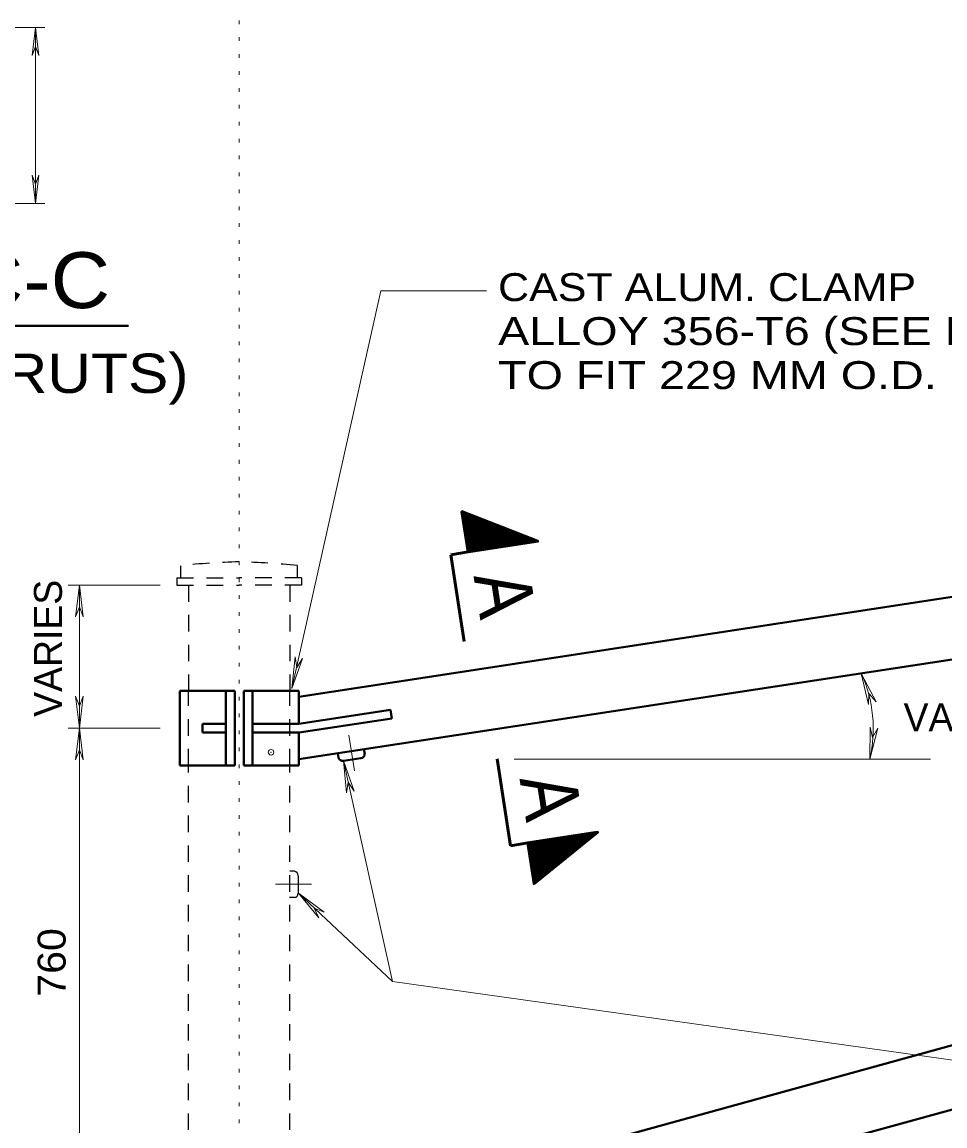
# Model space of a CAD drawing. Extents: x 312583 to 312854, y 144419 to 144597.
# Drawn here: x 312723.42 to 312748.5, y 144538.22 to 144568.25 of the extents above; entities that cross this region are included whole.
import ezdxf
from ezdxf.enums import TextEntityAlignment as Align

# ---------------------------------------------------------------- set-up
doc = ezdxf.new("R2010")
doc.units = 0
doc.header["$LTSCALE"] = 0.3
doc.header["$PDMODE"] = 32
doc.header["$PDSIZE"] = 0.15
doc.linetypes.add('DOTTED', pattern=[1.5, 0.3, -1.2])
doc.linetypes.add('SHORT_DASHED', pattern=[2.7, 1.5, -1.2])
doc.layers.add('1', color=7, linetype='Continuous', lineweight=13)

msp = doc.modelspace()

# ---------------------------------------------------------------- linework, layer by layer
at = {"layer": '1', "linetype": 'DOTTED'}
msp.add_line((312729.3174, 144527.7179), (312729.3174, 144572.2382), dxfattribs=at)
at = {"layer": '1'}
for p, q in [((312721.5945, 144568.1059), (312724.0325, 144568.1059)), ((312723.7795, 144568.1059), (312723.6875, 144567.3392)), ((312723.7795, 144563.3142), (312723.7795, 144568.1059)), ((312723.7795, 144568.1059), (312723.8715, 144567.3392)), ((312723.6875, 144567.3392), (312723.7795, 144567.5846)), ((312723.8715, 144567.3392), (312723.7795, 144567.5846)), ((312723.6875, 144564.0886), (312723.7795, 144563.8432)), ((312723.7795, 144563.3142), (312723.6875, 144564.0886)), ((312723.8715, 144564.0886), (312723.7795, 144563.8432)), ((312723.7795, 144563.3142), (312723.8715, 144564.0886)), ((312720.1991, 144563.3142), (312724.0325, 144563.3142)), ((312730.751, 144550.1199), (312733.166, 144560.9376)), ((312733.166, 144560.9376), (312736.041, 144560.9376)), ((312727.1707, 144552.9336), (312724.6685, 144552.9336)), ((312724.9722, 144552.9336), (312724.8649, 144552.0672)), ((312724.9722, 144549.0466), (312724.9722, 144552.9336)), ((312724.9722, 144552.9336), (312725.0795, 144552.0672)), ((312724.8649, 144552.0672), (312724.9722, 144552.3432)), ((312725.0795, 144552.0672), (312724.9722, 144552.3432)), ((312730.751, 144550.1199), (312730.8354, 144550.9862)), ((312730.751, 144550.1199), (312731.0424, 144550.9402)), ((312730.8354, 144550.9862), (312730.8814, 144550.6949)), ((312731.0424, 144550.9402), (312730.8814, 144550.6949)), ((312746.23, 144550.5339), (312746.4294, 144549.6829)), ((312746.23, 144550.5339), (312746.6364, 144549.7596)), ((312746.4294, 144549.6829), (312746.437, 144549.9819)), ((312746.6364, 144549.7596), (312746.437, 144549.9819)), ((312724.8649, 144549.9129), (312724.9722, 144549.6369)), ((312724.9722, 144549.0466), (312724.8649, 144549.9129)), ((312725.0795, 144549.9129), (312724.9722, 144549.6369)), ((312724.9722, 144549.0466), (312725.0795, 144549.9129)), ((312746.46, 144548.1956), (312746.4677, 144549.0696)), ((312746.4677, 144549.0696), (312746.5367, 144548.7859)), ((312727.1707, 144549.0466), (312724.6685, 144549.0466)), ((312724.9722, 144549.0466), (312724.8649, 144548.1802)), ((312724.9722, 144534.6716), (312724.9722, 144549.0466)), ((312724.9722, 144549.0466), (312725.0795, 144548.1802)), ((312732.2997, 144548.8549), (312732.453, 144547.8812)), ((312746.46, 144548.1956), (312746.6824, 144549.0389)), ((312746.6824, 144549.0389), (312746.5367, 144548.7859)), ((312724.8649, 144548.1802), (312724.9722, 144548.4562)), ((312725.0795, 144548.1802), (312724.9722, 144548.4562)), ((312733.488, 144542.1466), (312732.154, 144548.1496)), ((312732.154, 144548.1496), (312732.2384, 144547.2832)), ((312732.154, 144548.1496), (312732.4454, 144547.3292)), ((312736.7924, 144548.1956), (312748.1084, 144548.1956)), ((312732.2384, 144547.2832), (312732.2767, 144547.5746)), ((312732.4454, 144547.3292), (312732.2767, 144547.5746)), ((312730.3064, 144544.7992), (312731.2877, 144544.7992)), ((312730.9274, 144544.5539), (312731.4794, 144543.8792)), ((312730.9274, 144544.5539), (312731.625, 144544.0402)), ((312731.4794, 144543.8792), (312731.3567, 144544.1476)), ((312731.625, 144544.0402), (312731.3567, 144544.1476))]:
    msp.add_line(p, q, dxfattribs=at)
at = {"layer": '1', "lineweight": 40}
for p, q in [((312730.935, 144549.8976), (312834.251, 144565.6909)), ((312730.935, 144548.1956), (312834.504, 144564.0272)), ((312730.935, 144535.5226), (312830.111, 144562.8236)), ((312730.9427, 144533.7822), (312830.5557, 144561.2059)), ((312710.9077, 144559.989), (312726.3126, 144559.989)), ((312727.6997, 144550.0586), (312729.1947, 144550.0586)), ((312727.6997, 144549.0466), (312727.6997, 144550.0586)), ((312728.957, 144549.0466), (312728.957, 144550.0586)), ((312729.1947, 144549.0466), (312729.1947, 144550.0586)), ((312730.935, 144550.0586), (312729.44, 144550.0586)), ((312729.44, 144549.0466), (312729.44, 144550.0586)), ((312729.6777, 144549.0466), (312729.6777, 144550.0586)), ((312730.935, 144550.0586), (312730.935, 144549.1616)), ((312730.935, 144549.1616), (312733.4267, 144549.5449)), ((312733.4267, 144549.5449), (312733.465, 144549.3072)), ((312728.3207, 144549.1616), (312728.3207, 144548.9239)), ((312728.957, 144549.1616), (312728.3207, 144549.1616)), ((312730.935, 144549.1616), (312729.6777, 144549.1616)), ((312730.9504, 144548.9239), (312733.465, 144549.3072)), ((312727.6997, 144549.0466), (312727.6997, 144548.0269)), ((312728.957, 144548.9239), (312728.3207, 144548.9239)), ((312728.957, 144549.0466), (312728.957, 144548.0269)), ((312729.1947, 144549.0466), (312729.1947, 144548.0269)), ((312729.44, 144549.0466), (312729.44, 144548.0269)), ((312729.6777, 144549.0466), (312729.6777, 144548.0269)), ((312730.9504, 144548.9239), (312729.6777, 144548.9239)), ((312730.935, 144548.9239), (312730.935, 144548.0269)), ((312732.729, 144548.3412), (312732.706, 144548.4716)), ((312732.016, 144548.2339), (312732.0007, 144548.3566)), ((312732.154, 144548.1496), (312732.6217, 144548.2262))]:
    msp.add_line(p, q, dxfattribs=at)
at = {"layer": '1', "lineweight": 35}
for p, q in [((312735.3817, 144554.9039), (312735.3894, 144554.9192)), ((312735.3817, 144554.8579), (312735.4124, 144554.9192)), ((312735.397, 144554.8042), (312735.4354, 144554.9039)), ((312735.397, 144554.7582), (312735.4584, 144554.8962)), ((312735.4124, 144554.7046), (312735.4814, 144554.8886)), ((312735.4124, 144554.6739), (312735.4967, 144554.8809)), ((312735.42, 144554.6202), (312735.5197, 144554.8732)), ((312735.4277, 144554.5742), (312735.5504, 144554.8579)), ((312735.4354, 144554.5282), (312735.5657, 144554.8579)), ((312735.443, 144554.4822), (312735.5964, 144554.8426)), ((312735.4507, 144554.4286), (312735.6117, 144554.8426)), ((312735.4584, 144554.3826), (312735.6347, 144554.8272)), ((312735.466, 144554.3366), (312735.6654, 144554.8272)), ((312735.4737, 144554.2829), (312735.6807, 144554.8119)), ((312735.4814, 144554.2369), (312735.7037, 144554.8042)), ((312735.489, 144554.1909), (312735.719, 144554.7966)), ((312735.4967, 144554.1372), (312735.7497, 144554.7812)), ((312735.5044, 144554.0912), (312735.7727, 144554.7812)), ((312735.512, 144554.0452), (312735.788, 144554.7659)), ((312735.5197, 144554.0069), (312735.811, 144554.7582)), ((312735.5274, 144553.9532), (312735.834, 144554.7506)), ((312735.5274, 144553.9149), (312735.857, 144554.7352)), ((312735.5427, 144553.8612), (312735.8877, 144554.7352)), ((312735.558, 144553.8382), (312735.903, 144554.7199)), ((312735.5887, 144553.8459), (312735.926, 144554.7199)), ((312735.6194, 144553.8459), (312735.949, 144554.7046)), ((312735.6424, 144553.8536), (312735.9644, 144554.7046)), ((312735.673, 144553.8536), (312735.995, 144554.6892)), ((312735.696, 144553.8689), (312736.018, 144554.6892)), ((312735.7267, 144553.8689), (312736.0334, 144554.6739)), ((312735.7497, 144553.8689), (312736.0564, 144554.6662)), ((312735.7804, 144553.8766), (312736.087, 144554.6586)), ((312735.811, 144553.8766), (312736.1024, 144554.6432)), ((312735.834, 144553.8842), (312736.1254, 144554.6432)), ((312735.8647, 144553.8842), (312736.1484, 144554.6279)), ((312735.8877, 144553.8919), (312736.1714, 144554.6202)), ((312735.9107, 144553.8919), (312736.1944, 144554.6126)), ((312735.9414, 144553.9072), (312736.2174, 144554.5972)), ((312735.972, 144553.8996), (312736.2404, 144554.5972)), ((312735.995, 144553.9072), (312736.2557, 144554.5819)), ((312736.018, 144553.9072), (312736.2787, 144554.5819)), ((312736.0487, 144553.9149), (312736.3094, 144554.5666)), ((312736.0794, 144553.9226), (312736.3247, 144554.5589)), ((312736.11, 144553.9226), (312736.3477, 144554.5512)), ((312736.133, 144553.9302), (312736.3707, 144554.5436)), ((312736.1637, 144553.9302), (312736.386, 144554.5359)), ((312736.1867, 144553.9456), (312736.4244, 144554.5282)), ((312736.2174, 144553.9379), (312736.4397, 144554.5206)), ((312736.2404, 144553.9456), (312736.4627, 144554.5052)), ((312736.271, 144553.9456), (312736.4857, 144554.5052)), ((312736.3017, 144553.9532), (312736.5087, 144554.4899)), ((312736.3247, 144553.9532), (312736.5317, 144554.4822)), ((312736.3554, 144553.9609), (312736.5547, 144554.4746)), ((312736.386, 144553.9686), (312736.57, 144554.4669)), ((312736.409, 144553.9686), (312736.593, 144554.4592)), ((312736.4397, 144553.9762), (312736.616, 144554.4516)), ((312736.4704, 144553.9762), (312736.639, 144554.4362)), ((312736.4934, 144553.9839), (312736.662, 144554.4362)), ((312736.5164, 144553.9839), (312736.685, 144554.4209)), ((312736.5394, 144553.9916), (312736.708, 144554.4209)), ((312736.57, 144553.9992), (312736.7234, 144554.4056)), ((312736.6007, 144553.9992), (312736.754, 144554.3979)), ((312736.6237, 144554.0069), (312736.777, 144554.3902)), ((312736.6544, 144554.0069), (312736.7924, 144554.3749)), ((312736.6774, 144554.0146), (312736.8154, 144554.3672)), ((312736.708, 144554.0146), (312736.846, 144554.3596)), ((312736.731, 144554.0222), (312736.8614, 144554.3519)), ((312736.7617, 144554.0222), (312736.8844, 144554.3442)), ((312736.7924, 144554.0299), (312736.9074, 144554.3366)), ((312736.8154, 144554.0299), (312736.9227, 144554.3289)), ((312736.846, 144554.0376), (312736.961, 144554.3212)), ((312736.869, 144554.0376), (312736.9764, 144554.3136)), ((312736.8997, 144554.0452), (312736.9994, 144554.2982)), ((312736.9304, 144554.0529), (312737.0224, 144554.2982)), ((312736.9534, 144554.0529), (312737.0377, 144554.2829)), ((312736.984, 144554.0606), (312737.0607, 144554.2829)), ((312737.007, 144554.0606), (312737.0914, 144554.2676)), ((312737.0377, 144554.0682), (312737.1067, 144554.2522)), ((312737.0684, 144554.0682), (312737.1297, 144554.2522)), ((312737.099, 144554.0759), (312737.1527, 144554.2369)), ((312737.122, 144554.0759), (312737.1757, 144554.2292)), ((312737.1527, 144554.0836), (312737.1987, 144554.2216)), ((312737.168, 144554.0912), (312737.2217, 144554.2139)), ((312737.191, 144554.0912), (312737.2447, 144554.2062)), ((312737.2217, 144554.0989), (312737.26, 144554.1986)), ((312737.2524, 144554.0989), (312737.2907, 144554.1909)), ((312737.283, 144554.1066), (312737.3137, 144554.1756)), ((312737.306, 144554.1066), (312737.329, 144554.1756)), ((312737.3367, 144554.1142), (312737.352, 144554.1602)), ((312737.3597, 144554.1142), (312737.375, 144554.1602)), ((312737.3904, 144554.1219), (312737.398, 144554.1449)), ((312737.421, 144554.1296), (312737.421, 144554.1449)), ((312738.0267, 144546.0489), (312738.3564, 144545.6426)), ((312738.0574, 144546.0566), (312738.3794, 144545.6502)), ((312738.088, 144546.0566), (312738.387, 144545.6732)), ((312738.111, 144546.0642), (312738.41, 144545.6809)), ((312738.134, 144546.0642), (312738.433, 144545.6962)), ((312738.1647, 144546.0719), (312738.456, 144545.7116)), ((312738.1954, 144546.0719), (312738.4637, 144545.7269)), ((312738.226, 144546.0796), (312738.4867, 144545.7499)), ((312738.249, 144546.0796), (312738.5097, 144545.7576)), ((312738.2797, 144546.0872), (312738.5174, 144545.7729)), ((312738.3027, 144546.0872), (312738.5404, 144545.7959)), ((312738.3334, 144546.0949), (312738.5634, 144545.8036)), ((312738.3564, 144546.0949), (312738.571, 144545.8189)), ((312738.387, 144546.1026), (312738.594, 144545.8342)), ((312738.4177, 144546.1102), (312738.617, 144545.8496)), ((312738.4407, 144546.1102), (312738.6324, 144545.8649)), ((312738.4637, 144546.1179), (312738.6554, 144545.8802)), ((312738.4867, 144546.1179), (312738.6707, 144545.8879)), ((312738.5174, 144546.1256), (312738.6937, 144545.9109)), ((312738.548, 144546.1256), (312738.7167, 144545.9186)), ((312738.571, 144546.1332), (312738.7244, 144545.9416)), ((312738.6017, 144546.1332), (312738.7474, 144545.9492)), ((312738.6247, 144546.1409), (312738.7704, 144545.9722)), ((312738.6554, 144546.1486), (312738.7857, 144545.9876)), ((312738.686, 144546.1486), (312738.801, 144545.9952)), ((312738.7167, 144546.1562), (312738.824, 144546.0182)), ((312738.7397, 144546.1562), (312738.8394, 144546.0336)), ((312738.7704, 144546.1639), (312738.8624, 144546.0412)), ((312738.7934, 144546.1639), (312738.8777, 144546.0642)), ((312738.8164, 144546.1716), (312738.9007, 144546.0719)), ((312738.847, 144546.1716), (312738.916, 144546.0949)), ((312738.8777, 144546.1792), (312738.9314, 144546.1026)), ((312738.9084, 144546.1869), (312738.9544, 144546.1179)), ((312738.9314, 144546.1869), (312738.9697, 144546.1332)), ((312738.962, 144546.1946), (312738.9927, 144546.1486)), ((312738.985, 144546.1946), (312739.008, 144546.1639)), ((312739.0157, 144546.2022), (312739.0234, 144546.1792)), ((312739.0464, 144546.2022), (312739.0464, 144546.1869)), ((312737.168, 144545.8956), (312737.7584, 144545.1596)), ((312737.1757, 144545.9186), (312737.7737, 144545.1826)), ((312737.1757, 144545.8419), (312737.7354, 144545.1519)), ((312737.1834, 144545.8036), (312737.72, 144545.1289)), ((312737.191, 144545.7499), (312737.697, 144545.1212)), ((312737.2064, 144545.9262), (312737.7967, 144545.1902)), ((312737.237, 144545.9262), (312737.812, 144545.2056)), ((312737.26, 144545.9339), (312737.8274, 144545.2209)), ((312737.2907, 144545.9339), (312737.8504, 144545.2362)), ((312737.3137, 144545.9339), (312737.8734, 144545.2516)), ((312737.3444, 144545.9339), (312737.881, 144545.2669)), ((312737.3674, 144545.9492), (312737.904, 144545.2746)), ((312737.398, 144545.9492), (312737.927, 144545.2976)), ((312737.4287, 144545.9569), (312737.9424, 144545.3129)), ((312737.4517, 144545.9569), (312737.9577, 144545.3282)), ((312737.4824, 144545.9646), (312737.9807, 144545.3436)), ((312737.513, 144545.9722), (312738.0037, 144545.3589)), ((312737.536, 144545.9722), (312738.019, 144545.3742)), ((312737.5667, 144545.9722), (312738.0344, 144545.3896)), ((312737.5974, 144545.9799), (312738.0574, 144545.4049)), ((312737.6204, 144545.9876), (312738.0727, 144545.4202)), ((312737.6434, 144545.9876), (312738.0957, 144545.4279)), ((312737.674, 144545.9952), (312738.111, 144545.4509)), ((312737.7047, 144545.9952), (312738.1264, 144545.4586)), ((312737.7354, 144546.0029), (312738.1494, 144545.4739)), ((312737.7584, 144546.0029), (312738.1647, 144545.4892)), ((312737.789, 144546.0106), (312738.18, 144545.5046)), ((312737.812, 144546.0106), (312738.2107, 144545.5199)), ((312737.835, 144546.0182), (312738.226, 144545.5352)), ((312737.858, 144546.0259), (312738.2414, 144545.5506)), ((312737.8887, 144546.0259), (312738.2644, 144545.5659)), ((312737.9194, 144546.0336), (312738.2797, 144545.5812)), ((312737.9424, 144546.0336), (312738.3027, 144545.5966)), ((312737.973, 144546.0412), (312738.318, 144545.6119)), ((312738.0037, 144546.0412), (312738.3334, 144545.6196)), ((312737.1987, 144545.7039), (312737.674, 144545.1059)), ((312737.2064, 144545.6579), (312737.6664, 144545.0829)), ((312737.214, 144545.6119), (312737.6434, 144545.0752)), ((312737.2217, 144545.5582), (312737.6204, 144545.0522)), ((312737.2294, 144545.5122), (312737.6127, 144545.0369)), ((312737.2294, 144545.4662), (312737.5897, 144545.0292)), ((312737.2447, 144545.4126), (312737.5744, 144545.0062)), ((312737.2447, 144545.3666), (312737.5514, 144544.9986)), ((312737.2524, 144545.3282), (312737.536, 144544.9756)), ((312737.26, 144545.2746), (312737.5207, 144544.9679)), ((312737.2677, 144545.2286), (312737.49, 144544.9526)), ((312737.2754, 144545.1826), (312737.4747, 144544.9372)), ((312737.283, 144545.1366), (312737.4594, 144544.9219)), ((312737.2907, 144545.0829), (312737.4364, 144544.9066)), ((312737.2984, 144545.0446), (312737.421, 144544.8912)), ((312737.306, 144544.9909), (312737.398, 144544.8836)), ((312737.3137, 144544.9449), (312737.3827, 144544.8606)), ((312737.3214, 144544.8912), (312737.3674, 144544.8452)), ((312737.329, 144544.8452), (312737.3444, 144544.8376))]:
    msp.add_line(p, q, dxfattribs=at)
at = {"layer": '1', "lineweight": 53}
for p, q in [((312735.5427, 144553.8382), (312735.075, 144553.7616)), ((312735.4354, 144551.4002), (312735.075, 144553.7616)), ((312736.3324, 144548.2109), (312736.6927, 144545.8419)), ((312737.1604, 144545.9186), (312736.6927, 144545.8419))]:
    msp.add_line(p, q, dxfattribs=at)
at = {"layer": '1', "linetype": 'SHORT_DASHED', "lineweight": 25}
for p, q in [((312727.7304, 144553.1329), (312727.7304, 144553.4626)), ((312730.9044, 144553.1329), (312730.9044, 144553.4626)), ((312727.623, 144553.1329), (312729.3174, 144553.1329)), ((312727.623, 144553.1329), (312727.623, 144552.9336)), ((312731.0117, 144553.1329), (312729.3174, 144553.1329)), ((312731.0117, 144553.1329), (312731.0117, 144552.9336)), ((312727.623, 144552.9336), (312729.3174, 144552.9336)), ((312727.9374, 144552.9336), (312727.9374, 144550.0586)), ((312731.0117, 144552.9336), (312729.3174, 144552.9336)), ((312730.6974, 144552.9336), (312730.6974, 144550.0586)), ((312727.9374, 144548.0269), (312727.9374, 144550.0586)), ((312730.6974, 144548.0269), (312730.6974, 144550.0586)), ((312727.9374, 144535.6836), (312727.9374, 144548.0269)), ((312730.6974, 144535.6836), (312730.6974, 144548.0269))]:
    msp.add_line(p, q, dxfattribs=at)
at = {"layer": '1', "lineweight": 25}
for p, q in [((312730.82, 144545.1519), (312730.6974, 144545.1519)), ((312730.9274, 144544.5539), (312730.9274, 144545.0292)), ((312730.82, 144544.4312), (312730.6897, 144544.4312))]:
    msp.add_line(p, q, dxfattribs=at)
at = {"layer": '1', "lineweight": 53}
for points in [[(312735.5427, 144553.8382), (312735.374, 144554.9346), (312737.4364, 144554.1296)], [(312737.1604, 144545.9186), (312737.3367, 144544.8146), (312739.0617, 144546.2099)]]:
    msp.add_lwpolyline(points, close=True, dxfattribs=at)
at = {"layer": '1', "lineweight": 40}
for points in [[(312727.6997, 144548.0269), (312728.957, 144548.0269), (312729.1947, 144548.0269)], [(312730.935, 144548.0269), (312729.6777, 144548.0269), (312729.44, 144548.0269)]]:
    msp.add_lwpolyline(points, dxfattribs=at)
at = {"layer": '1'}
msp.add_lwpolyline([(312759.7694, 144538.4589), (312733.488, 144542.1466), (312730.9274, 144544.5539)], dxfattribs=at)
at = {"layer": '1', "linetype": 'SHORT_DASHED', "lineweight": 25}
for centre, start, end in [((312730.1364, 144528.7367), 91.89125, 95.56371), ((312728.4964, 144528.7367), 84.43629, 88.10875)]:
    msp.add_arc(centre, 24.8462, start, end, dxfattribs=at)
at = {"layer": '1'}
msp.add_arc((312742.9667, 144549.0309), 3.5904, 346.57037, 24.76396, dxfattribs=at)
at = {"layer": '1', "lineweight": 40}
for centre, start, end in [((312732.133, 144548.268), 195.83064, 278.98563), ((312732.6076, 144548.3409), 278.4852, 1.56735)]:
    msp.add_arc(centre, 0.1193, start, end, dxfattribs=at)
at = {"layer": '1', "lineweight": 25}
for centre, start, end in [((312730.8045, 144545.0324), 359.7352, 82.81735), ((312730.8044, 144544.5522), 277.08064, 0.23563)]:
    msp.add_arc(centre, 0.1193, start, end, dxfattribs=at)
at = {"layer": '1'}
msp.add_point((312730.1837, 144548.3872), dxfattribs=at)

# ---------------------------------------------------------------- texts
for s, height, width, p in [('SECTION C-C', 1.52, 1.1, (312711.2732, 144560.4701)), ('CAST ALUM. CLAMP', 0.76, 1.15, (312736.3554, 144560.6606)), ('ALLOY 356-T6 (SEE NOTE "C")', 0.76, 1.25, (312736.3554, 144559.4636)), ('TO FIT 229 MM O.D. SHAFT', 0.76, 1.25, (312736.3554, 144558.2666))]:
    msp.add_text(s, height=height, dxfattribs=dict(at, width=width)).set_placement(p)
at = {"layer": '1', "width": 1.15}
msp.add_text('(TYPICAL ALL STRUTS)', height=1.07, dxfattribs=at).set_placement((312718.7514, 144558.1626), align=Align.CENTER)
at = {"layer": '1'}
msp.add_text('VARIES', height=0.76, rotation=90, dxfattribs=at).set_placement((312724.4985, 144549.3519))
at = {"layer": '1', "width": 0.9}
for p in [(312735.7817, 144552.5734), (312737.0313, 144547.0611)]:
    msp.add_text('A', height=1.533, rotation=278.758, dxfattribs=at).set_placement(p, align=Align.CENTER)
at = {"layer": '1'}
msp.add_text('VARIES', height=0.76, dxfattribs=at).set_placement((312747.3802, 144548.9574))
at = {"layer": '1', "width": 1.1}
msp.add_text('760', height=0.76, rotation=90, dxfattribs=at).set_placement((312724.5989, 144541.7363))

doc.saveas('drawing.dxf')
